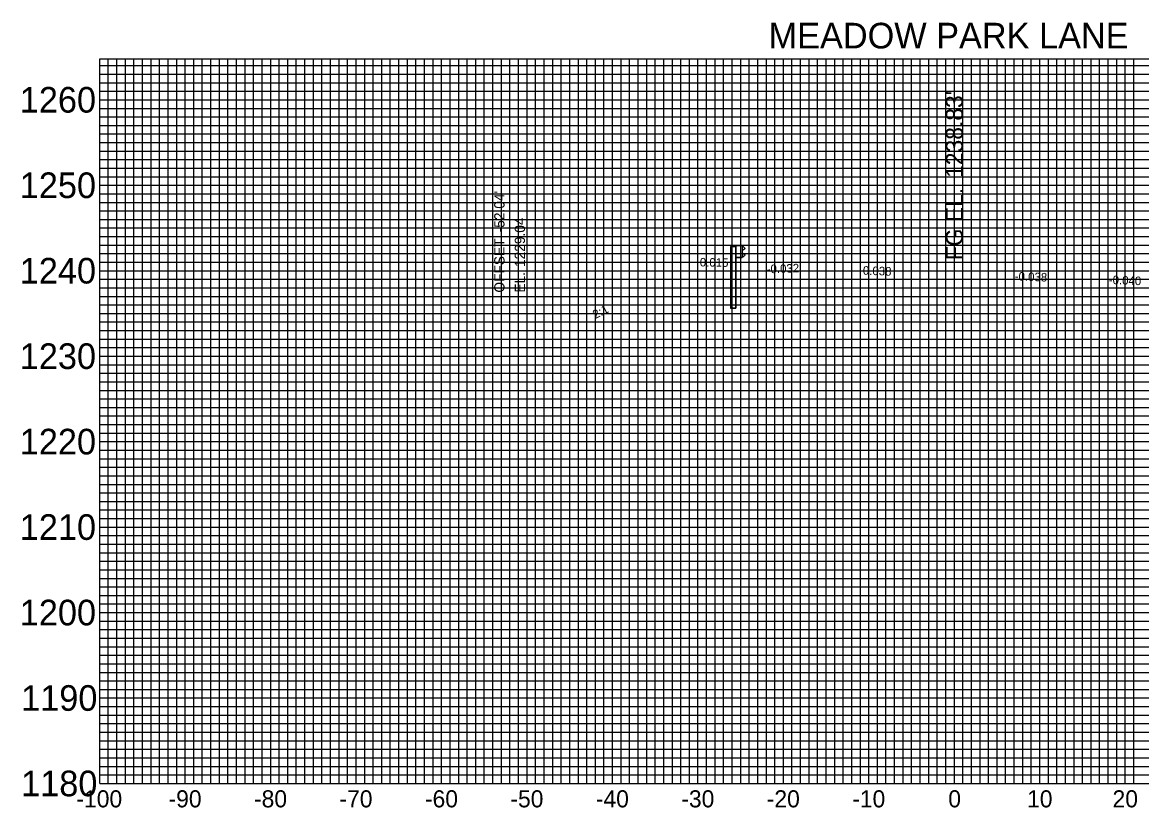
# Model space of a CAD drawing. Extents: x -109 to 149, y 1173 to 1269.
# Drawn here: x -109.1 to 21.9, y 1177.2 to 1269.1 of the extents above; entities that cross this region are included whole.
import ezdxf

# ---------------------------------------------------------------- set-up
doc = ezdxf.new("R2010")
doc.units = 0
for name, color, linetype in [('DES - SHEET - Light Grid', 7, 'Continuous'), ('DES - SHEET - Linework', 7, 'Continuous'), ('DES - XS - Proposed - Finished Grade Slopes Text', 7, 'Continuous'), ('DES - XS - Proposed - Guardrail', 7, 'Continuous'), ('DES - XS - Proposed - Text', 7, 'Continuous')]:
    doc.layers.add(name, color=color, linetype=linetype)

msp = doc.modelspace()

# ---------------------------------------------------------------- linework, layer by layer
at = {"layer": 'DES - SHEET - Light Grid'}
for p, q in [((-100, 1264), (140, 1264)), ((-99, 1180), (-99, 1264.81)), ((-98, 1180), (-98, 1264.81)), ((-97, 1180), (-97, 1264.81)), ((-96, 1180), (-96, 1264.81)), ((-95, 1180), (-95, 1264.81)), ((-94, 1180), (-94, 1264.81)), ((-93, 1180), (-93, 1264.81)), ((-92, 1180), (-92, 1264.81)), ((-91, 1180), (-91, 1264.81)), ((-89, 1180), (-89, 1264.81)), ((-88, 1180), (-88, 1264.81)), ((-87, 1180), (-87, 1264.81)), ((-86, 1180), (-86, 1264.81)), ((-85, 1180), (-85, 1264.81)), ((-84, 1180), (-84, 1264.81)), ((-83, 1180), (-83, 1264.81)), ((-82, 1180), (-82, 1264.81)), ((-81, 1180), (-81, 1264.81)), ((-79, 1180), (-79, 1264.81)), ((-78, 1180), (-78, 1264.81)), ((-77, 1180), (-77, 1264.81)), ((-76, 1180), (-76, 1264.81)), ((-75, 1180), (-75, 1264.81)), ((-74, 1180), (-74, 1264.81)), ((-73, 1180), (-73, 1264.81)), ((-72, 1180), (-72, 1264.81)), ((-71, 1180), (-71, 1264.81)), ((-69, 1180), (-69, 1264.81)), ((-68, 1180), (-68, 1264.81)), ((-67, 1180), (-67, 1264.81)), ((-66, 1180), (-66, 1264.81)), ((-65, 1180), (-65, 1264.81)), ((-64, 1180), (-64, 1264.81)), ((-63, 1180), (-63, 1264.81)), ((-62, 1180), (-62, 1264.81)), ((-61, 1180), (-61, 1264.81)), ((-59, 1180), (-59, 1264.81)), ((-58, 1180), (-58, 1264.81)), ((-57, 1180), (-57, 1264.81)), ((-56, 1180), (-56, 1264.81)), ((-55, 1180), (-55, 1264.81)), ((-54, 1180), (-54, 1264.81)), ((-53, 1180), (-53, 1264.81)), ((-52, 1180), (-52, 1264.81)), ((-51, 1180), (-51, 1264.81)), ((-49, 1180), (-49, 1264.81)), ((-48, 1180), (-48, 1264.81)), ((-47, 1180), (-47, 1264.81)), ((-46, 1180), (-46, 1264.81)), ((-45, 1180), (-45, 1264.81)), ((-44, 1180), (-44, 1264.81)), ((-43, 1180), (-43, 1264.81)), ((-42, 1180), (-42, 1264.81)), ((-41, 1180), (-41, 1264.81)), ((-39, 1180), (-39, 1264.81)), ((-38, 1180), (-38, 1264.81)), ((-37, 1180), (-37, 1264.81)), ((-36, 1180), (-36, 1264.81)), ((-35, 1180), (-35, 1264.81)), ((-34, 1180), (-34, 1264.81)), ((-33, 1180), (-33, 1264.81)), ((-32, 1180), (-32, 1264.81)), ((-31, 1180), (-31, 1264.81)), ((-29, 1180), (-29, 1264.81)), ((-28, 1180), (-28, 1264.81)), ((-27, 1180), (-27, 1264.81)), ((-26, 1180), (-26, 1264.81)), ((-25, 1180), (-25, 1264.81)), ((-24, 1180), (-24, 1264.81)), ((-23, 1180), (-23, 1264.81)), ((-22, 1180), (-22, 1264.81)), ((-21, 1180), (-21, 1264.81)), ((-19, 1180), (-19, 1264.81)), ((-18, 1180), (-18, 1264.81)), ((-17, 1180), (-17, 1264.81)), ((-16, 1180), (-16, 1264.81)), ((-15, 1180), (-15, 1264.81)), ((-14, 1180), (-14, 1264.81)), ((-13, 1180), (-13, 1264.81)), ((-12, 1180), (-12, 1264.81)), ((-11, 1180), (-11, 1264.81)), ((-9, 1180), (-9, 1264.81)), ((-8, 1180), (-8, 1264.81)), ((-7, 1180), (-7, 1264.81)), ((-6, 1180), (-6, 1264.81)), ((-5, 1180), (-5, 1264.81)), ((-4, 1180), (-4, 1264.81)), ((-3, 1180), (-3, 1264.81)), ((-2, 1180), (-2, 1264.81)), ((-1, 1180), (-1, 1264.81)), ((1, 1180), (1, 1264.81)), ((2, 1180), (2, 1264.81)), ((3, 1180), (3, 1264.81)), ((4, 1180), (4, 1264.81)), ((5, 1180), (5, 1264.81)), ((6, 1180), (6, 1264.81)), ((7, 1180), (7, 1264.81)), ((8, 1180), (8, 1264.81)), ((9, 1180), (9, 1264.81)), ((11, 1180), (11, 1264.81)), ((12, 1180), (12, 1264.81)), ((13, 1180), (13, 1264.81)), ((14, 1180), (14, 1264.81)), ((15, 1180), (15, 1264.81)), ((16, 1180), (16, 1264.81)), ((17, 1180), (17, 1264.81)), ((18, 1180), (18, 1264.81)), ((19, 1180), (19, 1264.81)), ((21, 1180), (21, 1264.81)), ((-100, 1263), (140, 1263)), ((-100, 1262), (140, 1262)), ((-100, 1261), (140, 1261)), ((-100, 1259), (140, 1259)), ((-100, 1258), (140, 1258)), ((-100, 1257), (140, 1257)), ((-100, 1256), (140, 1256)), ((-100, 1255), (140, 1255)), ((-100, 1254), (140, 1254)), ((-100, 1253), (140, 1253)), ((-100, 1252), (140, 1252)), ((-100, 1251), (140, 1251)), ((-100, 1249), (140, 1249)), ((-100, 1248), (140, 1248)), ((-100, 1247), (140, 1247)), ((-100, 1246), (140, 1246)), ((-100, 1245), (140, 1245)), ((-100, 1244), (140, 1244)), ((-100, 1243), (140, 1243)), ((-100, 1242), (140, 1242)), ((-100, 1241), (140, 1241)), ((-100, 1239), (140, 1239)), ((-100, 1238), (140, 1238)), ((-100, 1237), (140, 1237)), ((-100, 1236), (140, 1236)), ((-100, 1235), (140, 1235)), ((-100, 1234), (140, 1234)), ((-100, 1233), (140, 1233)), ((-100, 1232), (140, 1232)), ((-100, 1231), (140, 1231)), ((-100, 1229), (140, 1229)), ((-100, 1228), (140, 1228)), ((-100, 1227), (140, 1227)), ((-100, 1226), (140, 1226)), ((-100, 1225), (140, 1225)), ((-100, 1224), (140, 1224)), ((-100, 1223), (140, 1223)), ((-100, 1222), (140, 1222)), ((-100, 1221), (140, 1221)), ((-100, 1219), (140, 1219)), ((-100, 1218), (140, 1218)), ((-100, 1217), (140, 1217)), ((-100, 1216), (140, 1216)), ((-100, 1215), (140, 1215)), ((-100, 1214), (140, 1214)), ((-100, 1213), (140, 1213)), ((-100, 1212), (140, 1212)), ((-100, 1211), (140, 1211)), ((-100, 1209), (140, 1209)), ((-100, 1208), (140, 1208)), ((-100, 1207), (140, 1207)), ((-100, 1206), (140, 1206)), ((-100, 1205), (140, 1205)), ((-100, 1204), (140, 1204)), ((-100, 1203), (140, 1203)), ((-100, 1202), (140, 1202)), ((-100, 1201), (140, 1201)), ((-100, 1199), (140, 1199)), ((-100, 1198), (140, 1198)), ((-100, 1197), (140, 1197)), ((-100, 1196), (140, 1196)), ((-100, 1195), (140, 1195)), ((-100, 1194), (140, 1194)), ((-100, 1193), (140, 1193)), ((-100, 1192), (140, 1192)), ((-100, 1191), (140, 1191)), ((-100, 1189), (140, 1189)), ((-100, 1188), (140, 1188)), ((-100, 1187), (140, 1187)), ((-100, 1186), (140, 1186)), ((-100, 1185), (140, 1185)), ((-100, 1184), (140, 1184)), ((-100, 1183), (140, 1183)), ((-100, 1182), (140, 1182)), ((-100, 1181), (140, 1181))]:
    msp.add_line(p, q, dxfattribs=at)
at = {"layer": 'DES - SHEET - Linework'}
for p, q in [((-100, 1264.81), (140, 1264.81)), ((-100, 1180), (-100, 1264.81)), ((-90, 1180), (-90, 1264.81)), ((-80, 1180), (-80, 1264.81)), ((-70, 1180), (-70, 1264.81)), ((-60, 1180), (-60, 1264.81)), ((-50, 1180), (-50, 1264.81)), ((-40, 1180), (-40, 1264.81)), ((-30, 1180), (-30, 1264.81)), ((-20, 1180), (-20, 1264.81)), ((-10, 1180), (-10, 1264.81)), ((0, 1180), (0, 1264.81)), ((10, 1180), (10, 1264.81)), ((20, 1180), (20, 1264.81)), ((-100, 1260), (140, 1260)), ((-100, 1250), (140, 1250)), ((-100, 1240), (140, 1240)), ((-100, 1230), (140, 1230)), ((-100, 1220), (140, 1220)), ((-100, 1210), (140, 1210)), ((-100, 1200), (140, 1200)), ((-100, 1190), (140, 1190)), ((-100, 1180), (140, 1180))]:
    msp.add_line(p, q, dxfattribs=at)
at = {"layer": 'DES - XS - Proposed - Guardrail'}
for p, q in [((-24.84, 1242.94), (-25.59, 1242.94)), ((-25.59, 1242.94), (-25.59, 1242.94)), ((-25.59, 1242.94), (-24.84, 1242.94)), ((-25.59, 1242.94), (-25.59, 1241.54)), ((-25.59, 1242.94), (-25.59, 1241.54)), ((-24.84, 1242.94), (-24.84, 1242.94)), ((-24.84, 1242.94), (-24.84, 1241.54)), ((-24.84, 1242.94), (-24.84, 1241.54)), ((-26.16, 1242.82), (-26.18, 1242.82)), ((-26.18, 1242.82), (-26.18, 1242.82)), ((-26.18, 1242.82), (-26.16, 1242.82)), ((-26.18, 1242.82), (-26.18, 1235.62)), ((-26.18, 1242.82), (-26.18, 1235.62)), ((-25.61, 1242.82), (-26.16, 1242.82)), ((-26.16, 1242.82), (-26.16, 1242.82)), ((-26.16, 1242.82), (-26.16, 1242.82)), ((-26.16, 1242.82), (-25.61, 1242.82)), ((-26.16, 1242.82), (-26.16, 1235.62)), ((-26.16, 1242.82), (-26.16, 1235.62)), ((-26.16, 1242.82), (-26.16, 1235.62)), ((-26.16, 1242.82), (-26.16, 1235.62)), ((-25.59, 1242.82), (-25.61, 1242.82)), ((-25.61, 1242.82), (-25.61, 1242.82)), ((-25.61, 1242.82), (-25.61, 1242.82)), ((-25.61, 1242.82), (-25.59, 1242.82)), ((-25.61, 1242.82), (-25.61, 1235.62)), ((-25.61, 1242.82), (-25.61, 1235.62)), ((-25.61, 1242.82), (-25.61, 1235.62)), ((-25.61, 1242.82), (-25.61, 1235.62)), ((-25.59, 1242.82), (-25.59, 1242.82)), ((-25.59, 1242.82), (-25.59, 1235.62)), ((-25.59, 1242.82), (-25.59, 1235.62)), ((-24.83, 1242.84), (-24.79, 1242.83)), ((-24.83, 1242.28), (-24.83, 1242.17)), ((-24.79, 1241.62), (-24.83, 1241.61)), ((-24.54, 1242.53), (-24.79, 1242.36)), ((-24.79, 1242.09), (-24.54, 1241.91)), ((-24.67, 1242.78), (-24.54, 1242.69)), ((-24.54, 1241.76), (-24.67, 1241.67)), ((-24.84, 1241.54), (-25.59, 1241.54)), ((-25.59, 1241.54), (-25.59, 1241.54)), ((-25.59, 1241.54), (-24.84, 1241.54)), ((-24.84, 1241.54), (-24.84, 1241.54)), ((-26.16, 1235.62), (-26.18, 1235.62)), ((-26.18, 1235.62), (-26.18, 1235.62)), ((-26.18, 1235.62), (-26.16, 1235.62)), ((-25.61, 1235.62), (-26.16, 1235.62)), ((-26.16, 1235.62), (-26.16, 1235.62)), ((-26.16, 1235.62), (-26.16, 1235.62)), ((-26.16, 1235.62), (-25.61, 1235.62)), ((-25.59, 1235.62), (-25.61, 1235.62)), ((-25.61, 1235.62), (-25.61, 1235.62)), ((-25.61, 1235.62), (-25.61, 1235.62)), ((-25.61, 1235.62), (-25.59, 1235.62)), ((-25.59, 1235.62), (-25.59, 1235.62))]:
    msp.add_line(p, q, dxfattribs=at)
for centre, radius, start, end in [((-24.74, 1242.28), 0.0938, 125, 180), ((-24.74, 1242.17), 0.0937, 180, 235), ((-24.84, 1242.53), 0.3, 55, 80), ((-24.84, 1241.91), 0.3, 280, 305), ((-24.59, 1242.61), 0.0938, 305, 55), ((-24.59, 1241.84), 0.0938, 305, 55)]:
    msp.add_arc(centre, radius, start, end, dxfattribs=at)

# ---------------------------------------------------------------- texts
at = {"layer": 'DES - XS - Proposed - Finished Grade Slopes Text'}
for s, height, rotation, p in [("-52.04'", 1.2, 90, (-52.64, 1244.49)), ('1229.04', 1.2, 90, (-50.24, 1240.43)), ('OFFSET ', 1.2, 90, (-52.64, 1237.44)), ('0.015', 1, 359.1406, (-29.79, 1240.5)), ('-0.032', 1, 1.8328, (-21.94, 1239.69)), ('0.038', 1, 357.8238, (-10.72, 1239.54)), ('EL. ', 1.2, 90, (-50.24, 1237.44)), ('-0.038', 1, 357.8238, (7.05, 1238.87)), ('-0.040', 1, 357.7094, (18.06, 1238.45)), ('2:1', 1, 26.5651, (-42.02, 1234.35))]:
    msp.add_text(s, height=height, rotation=rotation, dxfattribs=at).set_placement(p)
at = {"layer": 'DES - XS - Proposed - Text'}
for s, height, p in [('MEADOW PARK LANE', 3, (-21.74, 1266.01)), ('1260', 3, (-109.36, 1258.5)), ('1250', 3, (-109.36, 1248.5)), ('1240', 3, (-109.36, 1238.5)), ('1230', 3, (-109.36, 1228.5)), ('1220', 3, (-109.36, 1218.5)), ('1210', 3, (-109.36, 1208.5)), ('1200', 3, (-109.36, 1198.5)), ('1190', 3, (-109.2, 1188.5)), ('1180', 3, (-109.2, 1178.5)), ('-100', 2, (-102.73, 1177.2)), ('-90', 2, (-91.95, 1177.2)), ('-80', 2, (-81.95, 1177.2)), ('-70', 2, (-71.95, 1177.2)), ('-60', 2, (-61.95, 1177.2)), ('-50', 2, (-51.95, 1177.2)), ('-40', 2, (-41.95, 1177.2)), ('-30', 2, (-31.95, 1177.2)), ('-20', 2, (-21.95, 1177.2)), ('-10', 2, (-11.95, 1177.2)), ('0', 2, (-0.71, 1177.2)), ('10', 2, (8.51, 1177.2)), ('20', 2, (18.51, 1177.2))]:
    msp.add_text(s, height=height, dxfattribs=at).set_placement(p)
for s, p in [("1238.83'", (1, 1250.86)), ('FG EL. ', (1, 1241.23))]:
    msp.add_text(s, height=2, rotation=90, dxfattribs=at).set_placement(p)

doc.saveas('drawing.dxf')
